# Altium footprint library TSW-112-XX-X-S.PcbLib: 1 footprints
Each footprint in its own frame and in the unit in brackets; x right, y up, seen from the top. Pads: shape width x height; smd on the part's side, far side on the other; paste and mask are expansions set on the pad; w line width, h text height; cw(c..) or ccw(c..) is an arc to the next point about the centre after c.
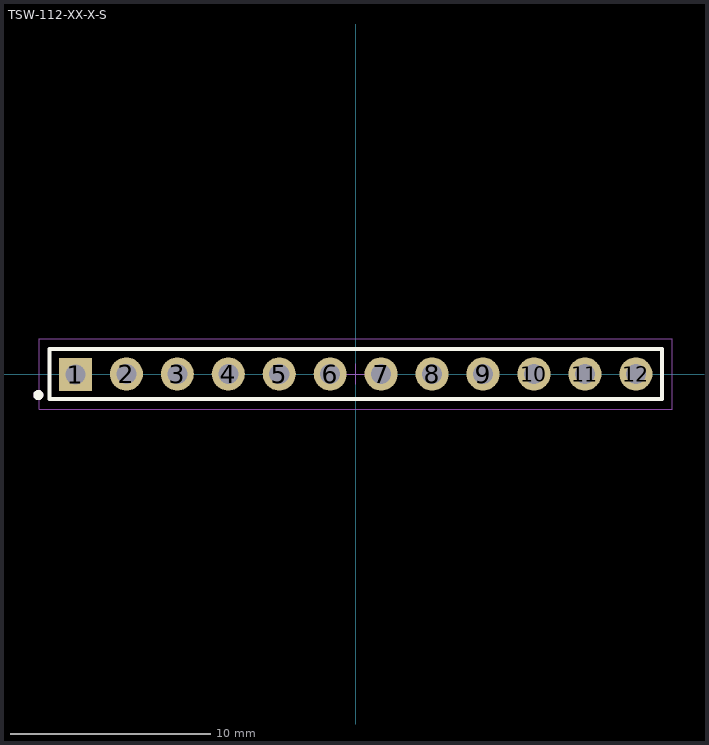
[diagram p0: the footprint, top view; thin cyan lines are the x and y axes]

## TSW-112-XX-X-S [mm] "2.54mm pitch, 12 pin, terminal strip; single row"
height 2.54
pads (12):
  rect 1.65x1.65 hole 1 mask+0: 1(-13.97,-0.025)
  round 1.65 hole 1 mask+0: 2(-11.43,0) 3(-8.89,0) 4(-6.35,0) 5(-3.81,0) 6(-1.27,0) 7(1.27,0) 8(3.81,0) 9(6.35,0) 10(8.89,0) 11(11.43,0) 12(13.97,0)
Top Overlay:
  circle w0.25: c-15.82,-1.05 r0.125
  lines w0.2: -15.27,-1.25 -15.27,1.25 15.28,1.25 15.28,-1.25 -15.27,-1.25
Mechanical 12:
  lines w0.001: -15.27,-1.25 -15.27,1.25 15.28,1.25 15.28,-1.25 -15.27,-1.25
Mechanical 13:
  circle w0.25: c-15.82,-1.05 r0.125
  lines w0.1: -15.27,-1.25 -15.27,1.25 15.28,1.25 15.28,-1.25 -15.27,-1.25
  text ".Designator" at 0,0 h1.52
Mechanical 15:
  lines w0.05: -0.5,0 0.5,0 ; 0,-0.5 0,0.5 ; -15.77,-1.75 -15.77,1.75 15.78,1.75 15.78,-1.75 -15.77,-1.75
